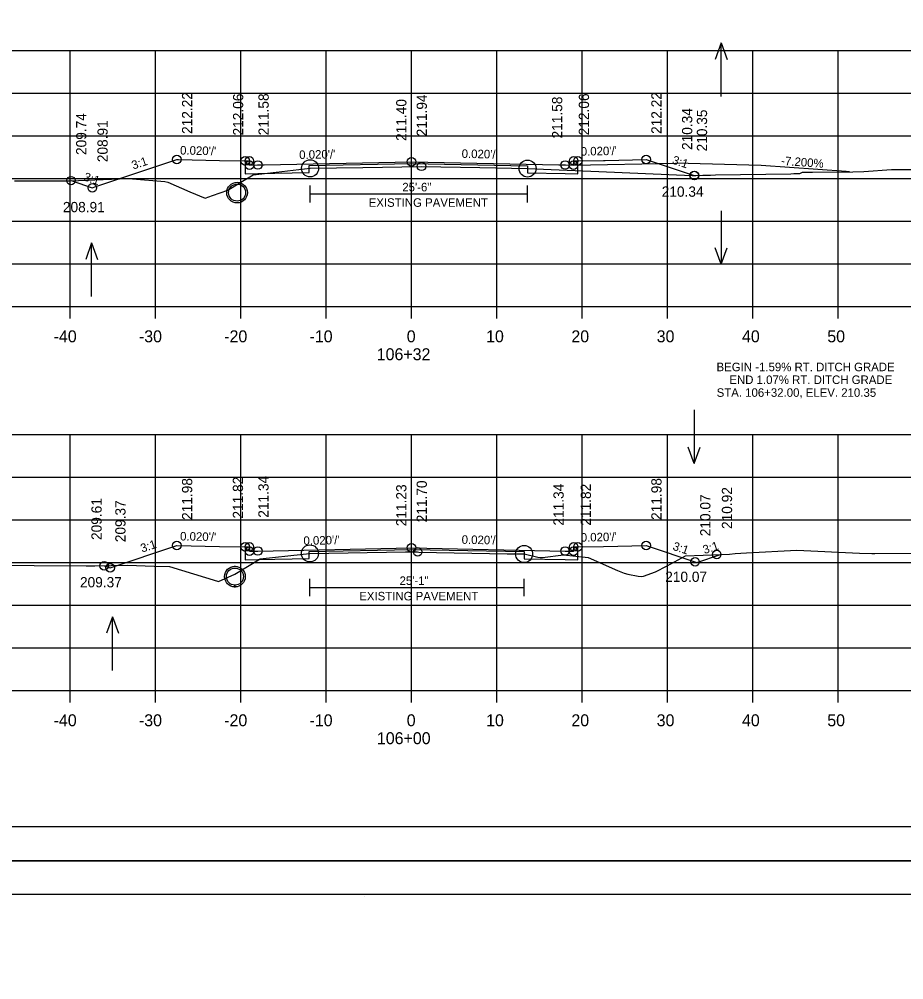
# Model space of a CAD drawing. Extents: x 1368968 to 1369915, y 377395 to 380381.
# Drawn here: x 1369092.1 to 1369195.8, y 378887.1 to 378999.7 of the extents above; entities that cross this region are included whole.
import ezdxf

# ---------------------------------------------------------------- set-up
doc = ezdxf.new("R2010")
doc.units = 0
for name, color, linetype in [('S_BORDER_NO_PLOT', 7, 'Continuous'), ('S_BREAKLINE_ANNOT', 7, 'Continuous'), ('S_BRIDGE', 7, 'Continuous'), ('S_BRIDGE_ANNOT', 7, 'Continuous'), ('S_CONTOUR_MAJOR', 7, 'Continuous'), ('S_CROSS_DRAIN', 7, 'Continuous'), ('S_CTL_TABLE', 7, 'Continuous'), ('S_CURB_ANNOT', 7, 'Continuous'), ('S_DITCHLINE_ANNOT', 7, 'Continuous'), ('S_DROP_INLET', 7, 'Continuous'), ('S_EXIST_ROW_ANNOT', 7, 'Continuous'), ('S_EXISTING_ALIGNMENT', 7, 'Continuous'), ('S_EXISTING_ALIGNMENT_ANNOT', 7, 'Continuous'), ('S_FENCE', 7, 'Continuous')]:
    doc.layers.add(name, color=color, linetype=linetype)

msp = doc.modelspace()

# ---------------------------------------------------------------- linework, layer by layer
at = {"layer": 'S_BORDER_NO_PLOT'}
for points in [[(1369118.62, 378983.1), (1369118.63, 378981.59), (1369120.13, 378981.62), (1369126.13, 378981.74), (1369126.13, 378982.57), (1369138.13, 378982.81), (1369151.73, 378982.54), (1369151.73, 378981.71), (1369156.13, 378981.62), (1369157.63, 378981.59), (1369157.64, 378983.1)], [(1369118.62, 378937.86), (1369118.63, 378936.35), (1369120.13, 378936.38), (1369126.13, 378936.5), (1369126.13, 378937.33), (1369138.13, 378937.57), (1369151.33, 378937.31), (1369151.33, 378936.48), (1369156.13, 378936.38), (1369157.63, 378936.35), (1369157.64, 378937.86)]]:
    msp.add_lwpolyline(points, dxfattribs=at)
at = {"layer": 'S_BREAKLINE_ANNOT'}
for p, q in [((1368998.13, 378966.04), (1369278.13, 378966.04)), ((1369098.13, 378964.64), (1369098.13, 378966.04)), ((1369108.13, 378964.64), (1369108.13, 378966.04)), ((1369118.13, 378964.64), (1369118.13, 378966.04)), ((1369128.13, 378964.64), (1369128.13, 378966.04)), ((1369138.13, 378964.64), (1369138.13, 378966.04)), ((1369148.13, 378964.64), (1369148.13, 378966.04)), ((1369158.13, 378964.64), (1369158.13, 378966.04)), ((1369168.13, 378964.64), (1369168.13, 378966.04)), ((1369178.13, 378964.64), (1369178.13, 378966.04)), ((1369188.13, 378964.64), (1369188.13, 378966.04)), ((1368998.13, 378921.04), (1369278.13, 378921.04)), ((1369098.13, 378919.64), (1369098.13, 378921.04)), ((1369108.13, 378919.64), (1369108.13, 378921.04)), ((1369118.13, 378919.64), (1369118.13, 378921.04)), ((1369128.13, 378919.64), (1369128.13, 378921.04)), ((1369138.13, 378919.64), (1369138.13, 378921.04)), ((1369148.13, 378919.64), (1369148.13, 378921.04)), ((1369158.13, 378919.64), (1369158.13, 378921.04)), ((1369168.13, 378919.64), (1369168.13, 378921.04)), ((1369178.13, 378919.64), (1369178.13, 378921.04)), ((1369188.13, 378919.64), (1369188.13, 378921.04))]:
    msp.add_line(p, q, dxfattribs=at)
at = {"layer": 'S_BRIDGE_ANNOT'}
for p, q in [((1369296.31, 378905.04), (1368980.13, 378905.04)), ((1368980.13, 378897.16), (1369296.31, 378897.16)), ((1369132.65, 378896.9), (1369132.65, 378896.9)), ((1369132.65, 378896.9), (1369132.65, 378896.9))]:
    msp.add_line(p, q, dxfattribs=at)
at = {"layer": 'S_CROSS_DRAIN'}
for p, q in [((1369157.13, 378982.6), (1369169.13, 378982.84)), ((1369179.13, 378982.58), (1369169.13, 378982.84)), ((1369126.24, 378979.23), (1369151.73, 378979.23)), ((1369126.22, 378933.1), (1369151.33, 378933.1))]:
    msp.add_line(p, q, dxfattribs=at)
msp.add_lwpolyline([(1369189.49, 378981.82), (1369189.1, 378981.86), (1369179.13, 378982.58)], dxfattribs=at)
at = {"layer": 'S_CTL_TABLE'}
for points in [[(1369091.59, 378980.75), (1369098.13, 378980.78), (1369102.95, 378980.96), (1369104.88, 378981.03), (1369105.02, 378981.03), (1369105.42, 378981), (1369109.22, 378980.7), (1369109.55, 378980.59), (1369112.15, 378979.48), (1369113.92, 378978.75), (1369114.78, 378979.06), (1369116.59, 378979.66), (1369117.93, 378980.48), (1369119.55, 378981.45), (1369122.28, 378981.76), (1369126.24, 378982.23), (1369132.43, 378982.34), (1369139.31, 378982.46), (1369146.13, 378982.32), (1369151.73, 378982.2), (1369160.09, 378981.86), (1369171.05, 378981.39), (1369171.45, 378981.4), (1369172.3, 378981.41), (1369173.17, 378981.43), (1369173.75, 378981.45), (1369182.6, 378981.6), (1369182.94, 378981.61), (1369183.65, 378981.64), (1369183.97, 378981.76), (1369185.13, 378981.77), (1369189.85, 378981.82), (1369191.17, 378981.84), (1369194.41, 378982.11), (1369199.21, 378982.1)], [(1369087.77, 378935.71), (1369099.98, 378935.64), (1369100.45, 378935.63), (1369100.81, 378935.63), (1369100.99, 378935.63), (1369104.83, 378935.71), (1369107.96, 378935.62), (1369109.75, 378935.56), (1369115.37, 378933.83), (1369115.51, 378933.79), (1369115.52, 378933.8), (1369117.43, 378934.67), (1369118.9, 378935.55), (1369120.38, 378936.48), (1369125.42, 378937.01), (1369126.22, 378937.1), (1369137.44, 378937.27), (1369138.85, 378937.29), (1369138.99, 378937.25), (1369149.36, 378937.04), (1369151.33, 378937.03), (1369152.93, 378936.64), (1369153.21, 378936.6), (1369153.48, 378936.63), (1369155.96, 378936.95), (1369158.83, 378936.6), (1369162.27, 378935.11), (1369163.04, 378934.78), (1369163.48, 378934.67), (1369164.71, 378934.45), (1369165.05, 378934.38), (1369165.33, 378934.45), (1369166.75, 378934.93), (1369168.11, 378935.63), (1369170.25, 378936.81), (1369174.41, 378936.98), (1369175.39, 378937.02), (1369176.08, 378937.09), (1369177.4, 378937.18), (1369183.32, 378937.49), (1369190.66, 378937.12), (1369192.09, 378937.1), (1369192.43, 378937.07), (1369205.66, 378937.11)]]:
    msp.add_lwpolyline(points, dxfattribs=at)
at = {"layer": 'S_CURB_ANNOT'}
for points in [[(1369098.21, 378980.79), (1369098.33, 378980.75), (1369100.71, 378979.95), (1369101.13, 378980.09), (1369110.62, 378983.26), (1369110.83, 378983.26), (1369115.62, 378983.16), (1369118.5, 378983.1), (1369118.62, 378983.1), (1369119.1, 378983.1), (1369119.12, 378983.1), (1369119.12, 378983.08), (1369119.13, 378982.6), (1369120.09, 378982.62), (1369120.13, 378982.62), (1369120.86, 378982.63), (1369138.13, 378982.98), (1369155.41, 378982.63), (1369156.13, 378982.62), (1369156.17, 378982.62), (1369157.13, 378982.6), (1369157.14, 378983.08), (1369157.14, 378983.1), (1369157.16, 378983.1), (1369157.64, 378983.1), (1369157.76, 378983.1), (1369160.64, 378983.16), (1369160.85, 378983.16), (1369165.64, 378983.26), (1369171.02, 378981.47), (1369171.27, 378981.38), (1369171.27, 378981.39), (1369171.3, 378981.4)], [(1369102.09, 378935.65), (1369102.8, 378935.42), (1369110.62, 378938.02), (1369115.62, 378937.92), (1369118.62, 378937.86), (1369119.12, 378937.86), (1369119.13, 378937.36), (1369120.13, 378937.38), (1369138.13, 378937.74), (1369156.13, 378937.38), (1369157.13, 378937.36), (1369157.14, 378937.86), (1369157.64, 378937.86), (1369160.64, 378937.92), (1369165.64, 378938.02), (1369171.57, 378936.05), (1369174.36, 378936.98)]]:
    msp.add_lwpolyline(points, dxfattribs=at)
at = {"layer": 'S_DITCHLINE_ANNOT'}
for p, q in [((1368998.13, 378996.04), (1369278.13, 378996.04)), ((1369098.13, 378966.04), (1369098.13, 378996.04)), ((1369108.13, 378966.04), (1369108.13, 378996.04)), ((1369118.13, 378966.04), (1369118.13, 378996.04)), ((1369128.13, 378966.04), (1369128.13, 378996.04)), ((1369138.13, 378966.04), (1369138.13, 378996.04)), ((1369148.13, 378966.04), (1369148.13, 378996.04)), ((1369158.13, 378966.04), (1369158.13, 378996.04)), ((1369168.13, 378966.04), (1369168.13, 378996.04)), ((1369178.13, 378966.04), (1369178.13, 378996.04)), ((1369188.13, 378966.04), (1369188.13, 378996.04)), ((1368998.13, 378991.04), (1369278.13, 378991.04)), ((1368998.13, 378986.04), (1369278.13, 378986.04)), ((1368998.13, 378981.04), (1369278.13, 378981.04)), ((1368998.13, 378976.04), (1369278.13, 378976.04)), ((1368998.13, 378971.04), (1369278.13, 378971.04)), ((1368998.13, 378966.04), (1369278.13, 378966.04)), ((1368998.13, 378951.04), (1369278.13, 378951.04)), ((1369098.13, 378921.04), (1369098.13, 378951.04)), ((1369108.13, 378921.04), (1369108.13, 378951.04)), ((1369118.13, 378921.04), (1369118.13, 378951.04)), ((1369128.13, 378921.04), (1369128.13, 378951.04)), ((1369138.13, 378921.04), (1369138.13, 378951.04)), ((1369148.13, 378921.04), (1369148.13, 378951.04)), ((1369158.13, 378921.04), (1369158.13, 378951.04)), ((1369168.13, 378921.04), (1369168.13, 378951.04)), ((1369178.13, 378921.04), (1369178.13, 378951.04)), ((1369188.13, 378921.04), (1369188.13, 378951.04)), ((1368998.13, 378946.04), (1369278.13, 378946.04)), ((1368998.13, 378941.04), (1369278.13, 378941.04)), ((1368998.13, 378936.04), (1369278.13, 378936.04)), ((1368998.13, 378931.04), (1369278.13, 378931.04)), ((1368998.13, 378926.04), (1369278.13, 378926.04)), ((1368998.13, 378921.04), (1369278.13, 378921.04))]:
    msp.add_line(p, q, dxfattribs=at)
at = {"layer": 'S_DROP_INLET'}
for p, q in [((1369117.35, 378935.59), (1369117.5, 378935.59)), ((1369117.35, 378933.18), (1369117.5, 378933.17)), ((1368967.73, 378901.06), (1369301.07, 378901.06)), ((1368967.73, 378901.06), (1369301.07, 378901.06))]:
    msp.add_line(p, q, dxfattribs=at)
for points in [[(1368967.73, 379114.4), (1369301.07, 379114.4), (1369301.07, 378901.06), (1368967.73, 378901.06)], [(1369214.05, 379110.5), (1369214.05, 379100.62), (1369249.79, 379100.62), (1369249.79, 379097.7), (1369272.99, 379097.7), (1369272.99, 379073.37), (1369296.31, 379073.37), (1369296.31, 378905.04), (1368980.13, 378905.04), (1368980.13, 379110.5)], [(1368967.73, 378901.06), (1369301.07, 378901.06), (1369301.07, 378687.72), (1368967.73, 378687.72)], [(1369214.05, 378897.16), (1369214.05, 378887.28), (1369249.79, 378887.28), (1369249.79, 378884.36), (1369272.99, 378884.36), (1369272.99, 378860.03), (1369296.31, 378860.03), (1369296.31, 378691.7), (1368980.13, 378691.7), (1368980.13, 378897.16)]]:
    msp.add_lwpolyline(points, close=True, dxfattribs=at)
for centre, radius in [((1369110.62, 378983.26), 0.5), ((1369118.62, 378983.1), 0.5), ((1369119.12, 378983.1), 0.5), ((1369138.13, 378982.98), 0.5), ((1369157.14, 378983.1), 0.5), ((1369157.64, 378983.1), 0.5), ((1369165.64, 378983.26), 0.5), ((1369119.13, 378982.6), 0.5), ((1369120.13, 378982.62), 0.5), ((1369120.13, 378982.62), 0.5), ((1369126.24, 378982.23), 1), ((1369139.31, 378982.46), 0.5), ((1369151.73, 378982.2), 1), ((1369156.13, 378982.62), 0.5), ((1369156.13, 378982.62), 0.5), ((1369157.13, 378982.6), 0.5), ((1369098.21, 378980.79), 0.5), ((1369171.27, 378981.38), 0.5), ((1369171.3, 378981.4), 0.5), ((1369100.71, 378979.95), 0.5), ((1369117.68, 378979.38), 1.21), ((1369110.62, 378938.02), 0.5), ((1369118.62, 378937.86), 0.5), ((1369119.12, 378937.86), 0.5), ((1369157.14, 378937.86), 0.5), ((1369157.64, 378937.86), 0.5), ((1369165.64, 378938.02), 0.5), ((1369119.13, 378937.36), 0.5), ((1369120.13, 378937.38), 0.5), ((1369120.13, 378937.38), 0.5), ((1369126.22, 378937.1), 1), ((1369138.13, 378937.74), 0.5), ((1369138.85, 378937.29), 0.5), ((1369151.33, 378937.03), 1), ((1369156.13, 378937.38), 0.5), ((1369156.13, 378937.38), 0.5), ((1369157.13, 378937.36), 0.5), ((1369173.91, 378936.96), 0.5), ((1369102.09, 378935.65), 0.5), ((1369171.37, 378936.11), 0.5), ((1369102.8, 378935.41), 0.5), ((1369117.43, 378934.38), 1.21)]:
    msp.add_circle(centre, radius, dxfattribs=at)
at = {"layer": 'S_EXIST_ROW_ANNOT'}
for p, q in [((1369126.24, 378978.23), (1369126.24, 378980.23)), ((1369151.73, 378978.23), (1369151.73, 378980.23)), ((1369117.35, 378935.38), (1369117.5, 378935.38)), ((1369126.22, 378932.1), (1369126.22, 378934.1)), ((1369151.33, 378932.1), (1369151.33, 378934.1)), ((1369117.35, 378933.38), (1369117.5, 378933.38))]:
    msp.add_line(p, q, dxfattribs=at)
for centre in [(1369117.68, 378979.38), (1369117.43, 378934.38)]:
    msp.add_circle(centre, 1, dxfattribs=at)
at = {"layer": 'S_EXISTING_ALIGNMENT'}
for p, q in [((1369174.44, 378996.92), (1369173.74, 378995)), ((1369174.44, 378990.63), (1369174.44, 378996.92)), ((1369174.44, 378996.92), (1369175.14, 378995)), ((1369174.44, 378977.26), (1369174.44, 378970.98)), ((1369100.63, 378973.48), (1369099.93, 378971.56)), ((1369100.63, 378967.2), (1369100.63, 378973.48)), ((1369100.63, 378973.48), (1369101.33, 378971.56)), ((1369174.44, 378970.98), (1369173.74, 378972.9)), ((1369174.44, 378970.98), (1369175.14, 378972.9)), ((1369171.28, 378953.92), (1369171.28, 378947.64)), ((1369171.28, 378947.64), (1369170.58, 378949.56)), ((1369171.28, 378947.64), (1369171.98, 378949.56)), ((1369103.07, 378929.67), (1369102.37, 378927.75)), ((1369103.07, 378923.39), (1369103.07, 378929.67)), ((1369103.07, 378929.67), (1369103.77, 378927.75))]:
    msp.add_line(p, q, dxfattribs=at)
at = {"layer": 'S_EXISTING_ALIGNMENT_ANNOT'}
for p, q in [((1369138.13, 378982.44), (1369138.13, 378992.44)), ((1369138.13, 378937.28), (1369138.13, 378947.28))]:
    msp.add_line(p, q, dxfattribs=at)

# ---------------------------------------------------------------- texts
at = {"layer": 'S_BRIDGE'}
for s, p in [('-40', (1369096.17, 378961.84)), ('-30', (1369106.17, 378961.84)), ('-20', (1369116.17, 378961.84)), ('-10', (1369126.17, 378961.84)), ('0', (1369137.57, 378961.84)), ('10', (1369146.87, 378961.84)), ('20', (1369156.87, 378961.84)), ('30', (1369166.87, 378961.84)), ('40', (1369176.87, 378961.84)), ('50', (1369186.87, 378961.84)), ('106+32', (1369134.05, 378959.74)), ('-40', (1369096.17, 378916.84)), ('-30', (1369106.17, 378916.84)), ('-20', (1369116.17, 378916.84)), ('-10', (1369126.17, 378916.84)), ('0', (1369137.57, 378916.84)), ('10', (1369146.87, 378916.84)), ('20', (1369156.87, 378916.84)), ('30', (1369166.87, 378916.84)), ('40', (1369176.87, 378916.84)), ('50', (1369186.87, 378916.84)), ('106+00', (1369134.07, 378914.74))]:
    msp.add_text(s, height=1.4, dxfattribs=at).set_placement(p)
at = {"layer": 'S_CONTOUR_MAJOR'}
for s, height, p in [('208.91', 1.2, (1369097.26, 378977.09)), ('BEGIN -1.59% RT. DITCH GRADE', 1, (1369173.89, 378958.45)), ('END 1.07% RT. DITCH GRADE', 1, (1369175.39, 378956.95)), ('STA. 106+32.00, ELEV. 210.35', 1, (1369173.9, 378955.45)), ('209.37', 1.2, (1369099.26, 378933.12))]:
    msp.add_text(s, height=height, dxfattribs=at).set_placement(p)
at = {"layer": 'S_CROSS_DRAIN'}
msp.add_text('-7.200%', height=1, rotation=355.8818, dxfattribs=at).set_placement((1369181.44, 378982.64))
at = {"layer": 'S_EXIST_ROW_ANNOT'}
for s, height, p in [('25\'-6"', 1, (1369137.05, 378979.53)), ('210.34', 1.2, (1369167.46, 378978.9)), ('EXISTING PAVEMENT', 1, (1369133.11, 378977.72)), ('210.07', 1.2, (1369167.87, 378933.76)), ('25\'-1"', 1, (1369136.73, 378933.4)), ('EXISTING PAVEMENT', 1, (1369132, 378931.59))]:
    msp.add_text(s, height=height, dxfattribs=at).set_placement(p)
at = {"layer": 'S_EXISTING_ALIGNMENT_ANNOT'}
for s, p in [('212.22', (1369112.42, 378986.26)), ('212.06', (1369118.4, 378986.08)), ('211.58', (1369121.39, 378986.1)), ('211.40', (1369137.53, 378985.44)), ('211.94', (1369139.93, 378985.98)), ('211.58', (1369155.8, 378985.73)), ('212.06', (1369158.94, 378986.1)), ('212.22', (1369167.44, 378986.26)), ('210.34', (1369171.04, 378984.38)), ('210.35', (1369172.78, 378984.21)), ('209.74', (1369100.01, 378983.79)), ('208.91', (1369102.51, 378982.95)), ('211.98', (1369112.42, 378941.02)), ('211.82', (1369118.38, 378941.18)), ('211.34', (1369121.37, 378941.28)), ('211.23', (1369137.53, 378940.28)), ('211.70', (1369139.93, 378940.74)), ('211.34', (1369155.97, 378940.36)), ('211.82', (1369159.16, 378940.35)), ('211.98', (1369167.44, 378941.02)), ('210.92', (1369175.71, 378939.96)), ('209.61', (1369101.8, 378938.67)), ('209.37', (1369104.6, 378938.41)), ('210.07', (1369173.17, 378939.11))]:
    msp.add_text(s, height=1.2, rotation=90, dxfattribs=at).set_placement(p)
at = {"layer": 'S_FENCE'}
for s, rotation, p in [("0.020'/'", 358.8543, (1369110.99, 378983.85)), ("0.020'/'", 1.1458, (1369157.98, 378983.71)), ('3:1', 18.4341, (1369105.51, 378982.08)), ("0.020'/'", 1.1458, (1369124.97, 378983.32)), ("0.020'/'", 358.8542, (1369144, 378983.46)), ('3:1', 341.5648, (1369168.61, 378982.8)), ('3:1', 341.5543, (1369099.62, 378980.84)), ("0.020'/'", 358.8543, (1369110.99, 378938.62)), ("0.020'/'", 1.1457, (1369157.98, 378938.47)), ('3:1', 18.4346, (1369106.55, 378937.19)), ("0.020'/'", 1.1457, (1369125.47, 378938.09)), ("0.020'/'", 358.8542, (1369144, 378938.23)), ('3:1', 341.5646, (1369168.67, 378937.54)), ('3:1', 18.4459, (1369172.48, 378937.01))]:
    msp.add_text(s, height=1, rotation=rotation, dxfattribs=at).set_placement(p)

doc.saveas('drawing.dxf')
